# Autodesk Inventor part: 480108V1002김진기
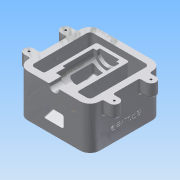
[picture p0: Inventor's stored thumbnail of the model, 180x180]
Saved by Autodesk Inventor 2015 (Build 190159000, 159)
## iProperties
Created: 2018-01
Part Number: 480108V1002김진기
Material: 알루미늄 6061
Document SubType Name: Modeling
Designer: Administrator
Density: 2.7 g/cm^3
Appearance: 알루미늄 - 평지
Mass: 956.404 g
Surface Area: 819.325 cm^2
Volume: 354.224 cm^3
Author: Administrator
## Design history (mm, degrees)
sketch "스케치1"
  geometry: L1 (-55, 55)-(55, 55); L2 (55, 55)-(55, -55); L3 (55, -55)-(-55, -55); L4 (-55, -55)-(-55, 55); L5 (-35.5, 55)-(-20.5, 55); L6 (35.5, 55)-(20.5, 55); 3 further points
  constraints: 12 end point, 4 point on line, 2 horizontal, 2 midpoint, 2 parallel, 1 collinear, 1 horizontal alignment, 1 perpendicular, 1 vertical alignment
  dimensions: "d0" = 110 distance of L2.end L3.end; "d1" = 110 distance of L3.end L1.start
extrude "돌출1" new body sketch "스케치1" stored distance "d6" = 65; taper "d7" = 0 deg
sketch "스케치3"
  geometry: L1 (-45, 45)-(45, 45); L2 (45, 45)-(45, -45); L3 (45, -45)-(-45, -45); L4 (-45, -45)-(-45, 45); 3 further points
  constraints: 8 end point, 2 midpoint, 2 parallel, 1 horizontal, 1 horizontal alignment, 1 perpendicular, 1 vertical alignment
  dimensions: "d16" = 90 distance of L1.start L1.end; "d17" = 90 distance of L1.end L2.end
extrude "돌출3" cut sketch "스케치3" stored distance "d18" = 20; taper "d19" = 0 deg
sketch "스케치2"
  geometry: L1 (-35.5, 65)-(-35.5, 55); L2 (-35.5, 55)-(-20.5, 55); L3 (-55, 55)-(55, 55) reference; L4 (-20.5, 55)-(-20.5, 65); L5 (20.5, 65)-(20.5, 55); L6 (20.5, 55)-(35.5, 55); L7 (35.5, 55)-(35.5, 65); L8 (0, 0)-(22.613, 0); L9 (20.5, -65)-(20.5, -55); L10 (35.5, -55)-(35.5, -65); L11 (-55, -55)-(55, -55); L12 (-35.5, -65)-(-35.5, -55); L13 (-20.5, -55)-(-20.5, -65); L14 (-35.5, -55)-(-20.5, -55); L15 (20.5, -55)-(35.5, -55); A1 r 7.5 centre (-28, 65) between (-20.5, 65) and (-35.5, 65); A2 r 7.5 centre (28, 65) between (35.5, 65) and (20.5, 65); A3 r 7.5 centre (28, -65) between (20.5, -65) and (35.5, -65); A4 r 7.5 centre (-28, -65) between (-35.5, -65) and (-20.5, -65)
  constraints: 28 end point, 12 symmetric about line, 8 point on circle, 8 point on line, 4 centre point, 3 parallel, 2 perpendicular, 2 tangent, 1 equal radius, 1 horizontal, 1 horizontal alignment, 1 vertical, 2 other
  dimensions: "d8" = 15 diameter of A1; "d9" = 27 horizontal distance of A1.centre L3.start; "d10" = 56 distance of A2.centre A1.centre; "d11" = 10 distance from line of L3 A1.centre
extrude "돌출2" join sketch "스케치2" distance "d12" = 20; taper "d13" = 0 deg
fillet "모깎기1" dims "d14" = 15
fillet "모깎기2" dims "d20" = 5
fillet "모깎기3" dims "d31" = 3
fillet "모깎기4" dims "d32" = 3
fillet "모깎기5" dims "d33" = 3
fillet "모깎기6" dims "d34" = 3
sketch "스케치6"
  geometry: L1 (-45, -40)-(-45, 40) reference; L2 (-45, 25)-(35, 25); L3 (35, 25)-(35, -25); L4 (35, -25)-(-45, -25); L5 (-45, -25)-(-45, 25); L6 (55, -40)-(55, 40) reference; 4 further points
  constraints: 8 end point, 3 midpoint, 2 parallel, 1 horizontal, 1 horizontal alignment, 1 perpendicular, 1 point on line, 1 vertical alignment
  dimensions: "d35" = 50 distance of L2.end L3.end; "d36" = 20 distance between parallel lines of L6 L3
extrude "돌출5" join sketch "스케치6" distance "d37" = 30; taper "d38" = 0 deg
sketch "스케치7"
  geometry: L1 (-35, 2.5)-(45, -18.936); L2 (45, -18.936)-(45, 2.5); L3 (45, 32.5)-(45, -32.5) reference; L4 (45, 2.5)-(-35, 2.5); L5 (45, 2.5)-(-35, 2.5) reference; 1 further point
  constraints: 6 end point, 2 collinear
  dimensions: "d39" = 105 deg angle of L3 L1
extrude "돌출6" join sketch "스케치7" stored distance "d40" = 50; taper "d41" = 0 deg
sketch "스케치8"
  geometry: 1 further point
fillet "모깎기7" dims "d42" = 3
fillet "모깎기8" dims "d43" = 3
sketch "스케치9"
  geometry: L1 (-32.776, 1.904)-(42.776, -18.34) reference; L2 (-20, 3.657)-(58.517, -17.381); L3 (-20, 3.657)-(-20, 23.44); L4 (-20, 23.44)-(17, 23.44); L5 (17, 23.44)-(17, 11.743); L6 (17, 11.743)-(58.517, 0.619); L7 (58.517, -17.381)-(58.517, 0.619); L8 (-55, 32.5)-(-55, -32.5) reference; L9 (55, -32.5)-(55, 32.5) reference; 2 further points
  constraints: 12 end point, 2 parallel, 2 vertical, 1 horizontal, 1 perpendicular
  dimensions: "d44" = 5 distance between parallel lines of L1 L2; "d45" = 18 distance of L2.end L6.end; "d46" = 37 distance of L3.end L4.end; "d66" = 11.69695 distance of L4.end L5.end; "d102" = 35 distance between parallel lines of L8 L3; "d103" = 41.51683 distance between parallel lines of L5 L7
extrude "돌출7" cut sketch "스케치9" stored distance "d50" = 30; taper "d51" = 0 deg
sketch "스케치10"
  geometry: L1 (55, 32.5)-(55, 25); L2 (55, 25)-(36, 25); L3 (36, 25)-(36, 16.5); L4 (36, 16.5)-(22, 16.5); L5 (22, 16.5)-(22, 12.5); L6 (22, 12.5)-(-25, 12.5); L7 (55, 32.5)-(-30, 32.5); L8 (40, 32.5)-(-40, 32.5) reference; L9 (-30, 32.5)-(-30, 17.5); L10 (-30, 17.5)-(-25, 17.5); L11 (-25, 12.5)-(-25, 17.5); L12 (-23.5, 12.5)-(-32.5, 12.5) reference; 2 further points
  constraints: 20 end point, 5 perpendicular, 2 vertical, 1 horizontal, 1 point on line
  dimensions: "d55" = 19 distance of L1.end L2.end; "d56" = 14 distance of L3.end L4.end; "d57" = 47 distance of L5.end L6.end; "d60" = 15 diameter of L2 L7; "d61" = 32 diameter of L4 L7; "d62" = 40 diameter of L6 L7; "d104" = 30 diameter of L10 L7; "d105" = 5 distance of L9.end L10.end
revolve "회전1" sketch "스케치10" stored, may be unused: angle "d63" = 90 deg
chamfer "모따기1" distance "d68" = 1; stored, may be unused: second distance "d69" = 2, angle "d70" = 45 deg
fillet "모깎기9" dims "d71" = 1
sketch "스케치11"
  geometry: L1 (55, -40)-(55, 40) reference; L2 (40, 55)-(38.5, 55) reference; L3 (-55, 40)-(-55, 8.5) reference; L4 (38.5, -55)-(40, -55) reference; 5 further points
  constraints: 2 horizontal alignment, 2 vertical alignment
  dimensions: "d76" = 27 distance from line of point (28, 65) L1; "d77" = 10 distance from line of point (28, 65) L2; "d78" = 27 distance from line of L3 point (-28, 65); "d79" = 10 distance from line of L4 point (28, -65)
hole "구멍1" sketch "스케치11" at (28, 65), (-28, 65), (-28, -65), (28, -65) diameter "d81" = 3.242; stored, may be unused: countersink angle "d85" = 90 deg, drill point angle "d87" = 118 deg; dims "d82" = 9, "d83" = 4, "d84" = 2, "d86" = 11
sketch "스케치12"
  geometry: L1 (16.136, 23.377)-(63.864, 23.377); L2 (63.864, 23.377)-(63.864, 16.623); L3 (63.864, 16.623)-(16.136, 16.623); L4 (16.136, 16.623)-(16.136, 23.377); L5 (-15, 65)-(-15, 0) reference; L6 (95, 0)-(80, 0) reference; 4 further points
  constraints: 2 midpoint, 1 horizontal alignment, 1 vertical alignment, 2 other
  dimensions: "d88" = 55 distance from line of L5 point (40, 20); "d89" = 20 distance from line of L6 point (40, 20); "d90" = 47.72772 distance of L1.start L1.end; "d91" = 6.75365 distance of L1.end L2.end; "d92" = 23.86386 horizontal distance of point (40, 23.377) point (63.864, 20)
feature "엠보싱1" sketch "스케치12" dims "d0" = 110, "d1" = 110, "d8" = 15, "d9" = 27, "d10" = 56, "d11" = 10, "d93" = 0.5, "d94" = 0
fillet "모깎기14" dims "d95" = 3
fillet "모깎기15" dims "d96" = 3
fillet "모깎기16" dims "d97" = 3
fillet "모깎기17" dims "d98" = 3
node "솔리드1"
